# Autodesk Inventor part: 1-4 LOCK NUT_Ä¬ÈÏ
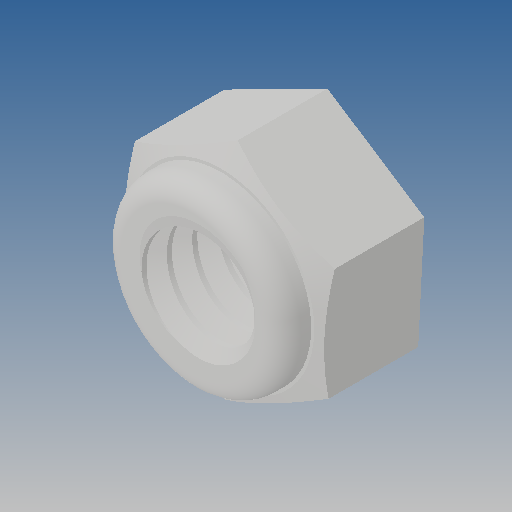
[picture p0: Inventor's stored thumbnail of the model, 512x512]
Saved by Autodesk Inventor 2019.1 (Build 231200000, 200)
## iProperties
Created: 2010-06
Part Number: 1-4 LOCK NUT_Ä¬ÈÏ
Material: Ogólny
Document SubType Name: Modeling
Designer: CADENGINEERING4
Density: 1 g/cm^3
Appearance: Domyślna
Author: CADENGINEERING4
Revision Number: ÈÎºÎ
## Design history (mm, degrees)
feature "NONE"
node "Bryła1"
